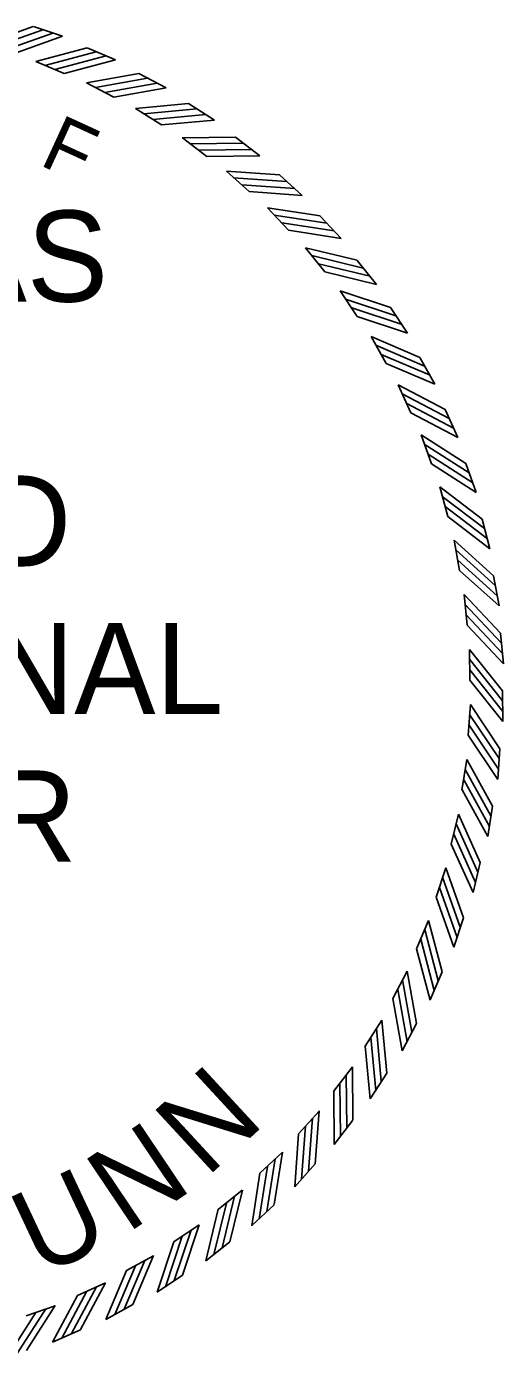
# Model space of a CAD drawing. Extents: x -35254 to 17396, y -8913 to 11592.
# Drawn here: x 9735 to 10581, y -5878 to -3515 of the extents above; entities that cross this region are included whole.
import ezdxf

# ---------------------------------------------------------------- set-up
doc = ezdxf.new("R2010")
doc.units = 0
doc.layers.add('STAMP', color=7, linetype='Continuous')

msp = doc.modelspace()

# ---------------------------------------------------------------- linework, layer by layer
at = {"layer": 'STAMP'}
for p, q in [((9746.6, -3514.6), (9798.3, -3531.8)), ((9842, -3552.4), (9892.1, -3573.8)), ((9750.9, -3576.4), (9801.1, -3597.9)), ((9841.2, -3614.4), (9889.5, -3640)), ((9934.1, -3598), (9982.2, -3623.4)), ((9928.2, -3659.7), (9974.2, -3689.2)), ((10022.1, -3651), (10067.9, -3680.4)), ((10011.1, -3712), (10054.5, -3745.2)), ((10105.3, -3711.1), (10148.6, -3744.2)), ((10089.3, -3771), (10129.8, -3807.6)), ((10183.4, -3777.9), (10223.8, -3814.4)), ((10162.5, -3836.3), (10199.8, -3876.1)), ((10255.6, -3850.9), (10292.9, -3890.6)), ((10230, -3907.3), (10263.9, -3950.1)), ((10321.6, -3929.6), (10355.5, -3972.3)), ((10291.4, -3983.7), (10321.7, -4029.2)), ((10380.9, -4013.5), (10411.1, -4058.8)), ((10346.3, -4065), (10372.7, -4112.7)), ((10433, -4102), (10459.3, -4149.6)), ((10394.2, -4150.4), (10416.6, -4200.2)), ((10477.6, -4194.5), (10500, -4244.2)), ((10435, -4239.6), (10453.2, -4291)), ((10514.5, -4290.3), (10532.6, -4341.7)), ((10468.3, -4331.8), (10482.2, -4384.6)), ((10543.3, -4388.9), (10557.1, -4441.6)), ((10493.8, -4426.4), (10503.3, -4480.2)), ((10563.8, -4489.5), (10573.3, -4543.2)), ((10511.5, -4522.8), (10516.5, -4577.2)), ((10576, -4591.5), (10581, -4645.8)), ((10521.1, -4620.3), (10521.6, -4675)), ((10579.7, -4694.2), (10580.2, -4748.6)), ((10522.6, -4718.4), (10518.6, -4772.8)), ((10575, -4796.8), (10571, -4851.1)), ((10516, -4816.1), (10507.5, -4870.1)), ((10501.4, -4913.1), (10488.5, -4966.1)), ((10561.7, -4898.6), (10553.3, -4952.4)), ((10478.8, -5008.4), (10461.6, -5060.3)), ((10540.1, -4999), (10527.3, -5052)), ((10448.4, -5101.6), (10427, -5151.8)), ((10510.3, -5097.3), (10493.1, -5149)), ((10410.5, -5192), (10384.9, -5240.3)), ((10472.5, -5192.8), (10451.1, -5242.9)), ((10365.2, -5278.9), (10335.7, -5324.9)), ((10426.9, -5284.8), (10401.4, -5333)), ((10312.9, -5361.8), (10279.7, -5405.2)), ((10373.9, -5372.8), (10344.5, -5418.7)), ((10253.9, -5440.1), (10217.3, -5480.6)), ((10313.8, -5456.1), (10280.7, -5499.4)), ((10188.6, -5513.2), (10148.8, -5550.6)), ((10247, -5534.1), (10210.5, -5574.5)), ((10117.5, -5580.7), (10074.8, -5614.7)), ((10174, -5606.4), (10134.3, -5643.6)), ((10041.1, -5642.1), (9995.7, -5672.4)), ((10095.3, -5672.3), (10052.6, -5706.2)), ((9959.9, -5697), (9912.1, -5723.4)), ((10011.4, -5731.6), (9966.1, -5761.8)), ((9874.5, -5745), (9824.7, -5767.4)), ((9785.3, -5785.8), (9733.8, -5804)), ((9922.9, -5783.7), (9875.3, -5810.1)), ((9830.4, -5828.4), (9780.7, -5850.7))]:
    msp.add_line(p, q, dxfattribs=at)
for points in [[(9657.6, -3546.1), (9746.5, -3514.6)], [(9674.2, -3551.8), (9763.1, -3520.3)], [(9692.3, -3557.4), (9781.1, -3525.9)], [(9709.5, -3563.3), (9798.3, -3531.7)], [(9750.8, -3576.5), (9842, -3552.4)], [(9766.9, -3583.5), (9858, -3559.4)], [(9784.4, -3590.6), (9875.6, -3566.5)], [(9801.1, -3597.9), (9892.2, -3573.8)], [(9841.2, -3614.4), (9934, -3598)], [(9856.6, -3622.8), (9949.4, -3606.3)], [(9873.5, -3631.3), (9966.3, -3614.8)], [(9889.5, -3639.9), (9982.3, -3623.4)], [(9928.1, -3659.7), (10022, -3651)], [(9942.8, -3669.3), (10036.6, -3660.6)], [(9958.9, -3679.2), (10052.8, -3670.4)], [(9974.1, -3689.1), (10068, -3680.4)], [(10011, -3712), (10105.2, -3711.1)], [(10024.8, -3722.8), (10119.1, -3721.8)], [(10040.1, -3734), (10134.4, -3733)], [(10054.4, -3745.1), (10148.7, -3744.2)], [(10089.2, -3771), (10183.3, -3777.8)], [(10102.1, -3782.9), (10196.2, -3789.7)], [(10116.5, -3795.3), (10210.5, -3802.1)], [(10129.8, -3807.6), (10223.9, -3814.4)], [(10162.4, -3836.3), (10255.5, -3850.8)], [(10174.3, -3849.2), (10267.4, -3863.7)], [(10187.5, -3862.7), (10280.7, -3877.3)], [(10199.8, -3876), (10293, -3890.6)], [(10229.9, -3907.3), (10321.5, -3929.5)], [(10240.7, -3921.2), (10332.3, -3943.4)], [(10252.7, -3935.7), (10344.4, -3957.9)], [(10263.9, -3950.1), (10355.5, -3972.3)], [(10291.3, -3983.7), (10380.8, -4013.4)], [(10300.9, -3998.4), (10390.4, -4028.1)], [(10311.7, -4013.9), (10401.2, -4043.6)], [(10321.7, -4029.1), (10411.1, -4058.8)], [(10346.2, -4064.9), (10432.9, -4101.9)], [(10354.5, -4080.3), (10441.2, -4117.3)], [(10364, -4096.7), (10450.8, -4133.7)], [(10372.7, -4112.7), (10459.4, -4149.7)], [(10394.2, -4150.4), (10477.5, -4194.4)], [(10401.2, -4166.4), (10484.6, -4210.5)], [(10409.4, -4183.5), (10492.7, -4227.6)], [(10416.6, -4200.2), (10500, -4244.2)], [(10434.9, -4239.5), (10514.4, -4290.3)], [(10440.6, -4256.1), (10520.1, -4306.9)], [(10447.3, -4273.8), (10526.8, -4324.6)], [(10453.2, -4291), (10532.7, -4341.7)], [(10468.2, -4331.7), (10543.2, -4388.9)], [(10472.5, -4348.7), (10547.5, -4405.9)], [(10477.7, -4366.9), (10552.7, -4424)], [(10482.2, -4384.5), (10557.2, -4441.6)], [(10493.8, -4426.3), (10563.8, -4489.5)], [(10496.6, -4443.6), (10566.6, -4506.8)], [(10500.3, -4462.2), (10570.3, -4525.3)], [(10503.3, -4480.1), (10573.3, -4543.2)], [(10511.4, -4522.7), (10576, -4591.5)], [(10512.8, -4540.2), (10577.4, -4608.9)], [(10515, -4559), (10579.6, -4627.7)], [(10516.5, -4577.1), (10581.1, -4645.8)], [(10521, -4620.3), (10579.7, -4694.1)], [(10521, -4637.8), (10579.7, -4711.6)], [(10521.6, -4656.7), (10580.3, -4730.5)], [(10521.6, -4674.9), (10580.3, -4748.7)], [(10522.6, -4718.3), (10574.9, -4796.7)], [(10521.1, -4735.8), (10573.5, -4814.2)], [(10518.6, -4772.8), (10571, -4851.2)], [(10520.1, -4754.7), (10572.5, -4833.1)], [(10516, -4816.1), (10561.7, -4898.5)], [(10513.1, -4833.4), (10558.8, -4915.8)], [(10510.6, -4852.1), (10556.3, -4934.6)], [(10507.6, -4870), (10553.3, -4952.5)], [(10501.4, -4913), (10540.1, -4998.9)], [(10497.1, -4930), (10535.8, -5015.9)], [(10493, -4948.5), (10531.7, -5034.4)], [(10488.5, -4966.1), (10527.3, -5052)], [(10478.8, -5008.4), (10510.3, -5097.2)], [(10473.1, -5025), (10504.6, -5113.8)], [(10467.5, -5043), (10499, -5131.9)], [(10461.6, -5060.2), (10493.1, -5149.1)], [(10448.4, -5101.6), (10472.5, -5192.7)], [(10441.4, -5117.6), (10465.5, -5208.8)], [(10434.3, -5135.2), (10458.4, -5226.3)], [(10427, -5151.8), (10451.1, -5243)], [(10410.5, -5191.9), (10426.9, -5284.7)], [(10402.1, -5207.3), (10418.6, -5300.2)], [(10385, -5240.2), (10401.5, -5333.1)], [(10393.6, -5224.3), (10410.1, -5317.1)], [(10365.2, -5278.8), (10373.9, -5372.7)], [(10345.7, -5309.7), (10354.5, -5403.6)], [(10355.6, -5293.5), (10364.3, -5387.4)], [(10335.8, -5324.9), (10344.5, -5418.7)], [(10312.9, -5361.7), (10313.8, -5456)], [(10302.1, -5375.6), (10303, -5469.8)], [(10279.8, -5405.2), (10280.7, -5499.4)], [(10290.9, -5390.9), (10291.9, -5485.1)], [(10242, -5452.9), (10235.2, -5546.9)], [(10253.9, -5440), (10247, -5534)], [(10217.3, -5480.6), (10210.5, -5574.6)], [(10229.6, -5467.2), (10222.8, -5561.2)], [(10175.7, -5525), (10161.2, -5618.2)], [(10188.6, -5513.1), (10174.1, -5606.3)], [(10148.9, -5550.6), (10134.3, -5643.7)], [(10162.2, -5538.3), (10147.6, -5631.4)], [(10103.7, -5591.4), (10081.5, -5683)], [(10117.6, -5580.6), (10095.4, -5672.3)], [(10074.8, -5614.6), (10052.6, -5706.3)], [(10089.2, -5603.5), (10066.9, -5695.1)], [(10041.2, -5642), (10011.5, -5731.5)], [(10011, -5662.5), (9981.3, -5752)], [(10026.5, -5651.6), (9996.8, -5741.1)], [(9995.8, -5672.4), (9966.1, -5761.9)], [(9928.2, -5714.8), (9891.2, -5801.5)], [(9944.5, -5705.3), (9907.6, -5792)], [(9960, -5696.9), (9923, -5783.6)], [(9912.2, -5723.4), (9875.2, -5810.2)], [(9841.4, -5760.1), (9797.3, -5843.5)], [(9858.4, -5752), (9814.4, -5835.3)], [(9874.5, -5744.9), (9830.5, -5828.3)], [(9785.4, -5785.7), (9734.6, -5865.1)], [(9824.7, -5767.4), (9780.7, -5850.8)], [(9751.1, -5798.1), (9700.3, -5877.5)], [(9768.8, -5791.4), (9718, -5870.8)]]:
    msp.add_lwpolyline(points, dxfattribs=at)

# ---------------------------------------------------------------- texts
for s, height, rotation, p in [('F', 99.1, 335.3628, (9754.8, -3759.1)), ('N', 150.5, 42.6817, (10053.4, -5560)), ('N', 150.5, 33.9264, (9912.4, -5658.8)), ('U', 150.5, 25.1712, (9758, -5735))]:
    msp.add_text(s, height=height, rotation=rotation, dxfattribs=at).set_placement(p)
for s, height, p in [('ARKANSAS', 161.78, (8701.1, -4003)), ('LICENSED', 161.78, (8731.9, -4473.2)), ('PROFESSIONAL', 161.779, (8400.7, -4735.2)), ('ENGINEER', 161.78, (8693.4, -4997.1))]:
    msp.add_text(s, height=height, dxfattribs=at).set_placement(p)

doc.saveas('drawing.dxf')
